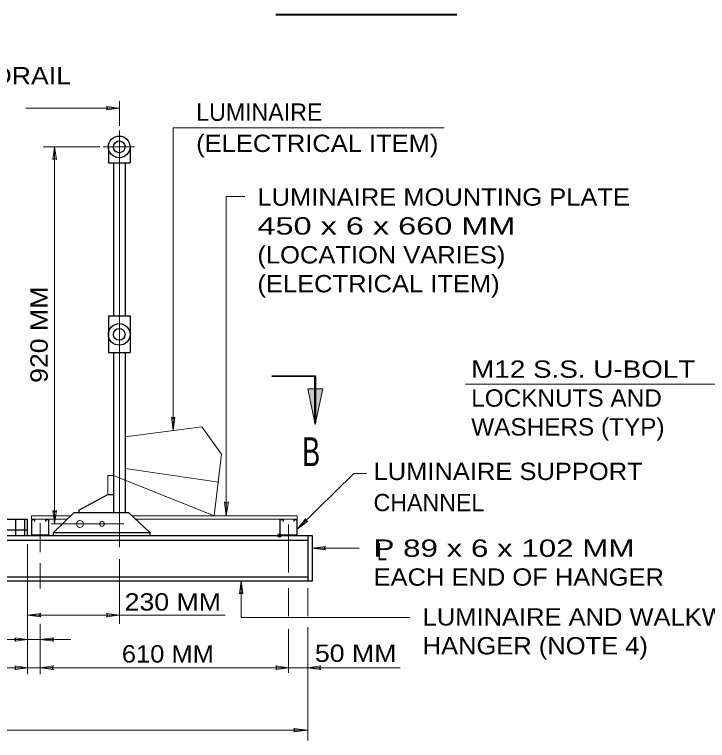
# Model space of a CAD drawing. Extents: x 312601.858 to 312602.699, y 144420.109 to 144420.704.
# Drawn here: x 312602.0414 to 312602.1613, y 144420.4587 to 144420.5844 of the extents above; entities that cross this region are included whole.
import ezdxf
from ezdxf.enums import TextEntityAlignment as Align

# ---------------------------------------------------------------- set-up
doc = ezdxf.new("R2010")
doc.units = 0
doc.header["$LTSCALE"] = 0.0012
doc.header["$PDMODE"] = 32
doc.header["$PDSIZE"] = 0.0006
doc.linetypes.add('DOT_DASHED', pattern=[7.7, 5, -1.2, 0.3, -1.2])
doc.linetypes.add('LONG_DASHED', pattern=[7.5, 6, -1.5])
for name, color, linetype, lineweight in [('1', 7, 'Continuous', 13), ('2', 7, 'Continuous', 13), ('39', 7, 'Continuous', 13), ('5', 7, 'Continuous', 25)]:
    doc.layers.add(name, color=color, linetype=linetype, lineweight=lineweight)

msp = doc.modelspace()

# ---------------------------------------------------------------- hatches: boundary and pattern name
at = {"layer": '1'}
for points in [[(312602.0921, 144420.5196), (312602.0934, 144420.5196), (312602.0934, 144420.5134)], [(312602.0921, 144420.5196), (312602.0934, 144420.5196), (312602.0934, 144420.5134)], [(312602.0947, 144420.5196), (312602.0934, 144420.5196), (312602.0934, 144420.5134)], [(312602.0947, 144420.5196), (312602.0934, 144420.5196), (312602.0934, 144420.5134)]]:
    msp.add_hatch(color=256, dxfattribs=at).paths.add_polyline_path(points)
at = {"layer": '39'}
for points in [[(312602.078, 144420.4998), (312602.0784, 144420.5), (312602.078, 144420.4976), (312602.0777, 144420.5)], [(312602.0899, 144420.4605), (312602.0897, 144420.4608), (312602.0921, 144420.4605), (312602.0897, 144420.4602)], [(312602.0899, 144420.4605), (312602.0897, 144420.4608), (312602.0921, 144420.4605), (312602.0897, 144420.4602)]]:
    msp.add_hatch(color=256, dxfattribs=at).paths.add_polyline_path(points)

# ---------------------------------------------------------------- linework, layer by layer
at = {"layer": '1'}
for p, q in [((312602.0595, 144420.5694), (312602.0595, 144420.5651)), ((312602.0433, 144420.5682), (312602.0595, 144420.5682)), ((312602.0688, 144420.5648), (312602.1157, 144420.5648)), ((312602.0688, 144420.5648), (312602.0688, 144420.5124)), ((312602.0463, 144420.5615), (312602.0561, 144420.5615)), ((312602.0483, 144420.5615), (312602.0483, 144420.4962)), ((312602.078, 144420.5529), (312602.078, 144420.4976)), ((312602.078, 144420.5529), (312602.0812, 144420.5529)), ((312602.0935, 144420.5137), (312602.0935, 144420.5217)), ((312602.1194, 144420.5204), (312602.1734, 144420.5204)), ((312602.0903, 144420.4976), (312602.0903, 144420.497)), ((312602.0477, 144420.4962), (312602.0603, 144420.4962)), ((312602.0436, 144420.4702), (312602.0436, 144420.4927)), ((312602.0929, 144420.492), (312602.101, 144420.492)), ((312602.0595, 144420.4901), (312602.0595, 144420.4789)), ((312602.0458, 144420.4894), (312602.0458, 144420.485)), ((312602.0806, 144420.48), (312602.0806, 144420.4863)), ((312602.0921, 144420.4851), (312602.0921, 144420.4802)), ((312602.0436, 144420.4804), (312602.0778, 144420.4804)), ((312602.0806, 144420.48), (312602.1098, 144420.48)), ((312602.0458, 144420.4789), (312602.0458, 144420.4702)), ((312602.0888, 144420.478), (312602.0888, 144420.4704)), ((312602.0921, 144420.4783), (312602.0921, 144420.4587)), ((312601.9943, 144420.4713), (312602.0436, 144420.4713)), ((312602.0436, 144420.4713), (312602.0888, 144420.4713)), ((312601.967, 144420.4605), (312602.0921, 144420.4605))]:
    msp.add_line(p, q, dxfattribs=at)
at = {"layer": '1', "linetype": 'DOT_DASHED'}
for p, q in [((312602.0595, 144420.5643), (312602.0595, 144420.4922)), ((312602.0567, 144420.5615), (312602.0621, 144420.5615)), ((312602.0458, 144420.4963), (312602.0458, 144420.4913)), ((312602.0888, 144420.4961), (312602.0888, 144420.4878)), ((312602.0888, 144420.4851), (312602.0888, 144420.4802))]:
    msp.add_line(p, q, dxfattribs=at)
at = {"layer": '1', "lineweight": 25}
for p, q in [((312602.0576, 144420.5615), (312602.0576, 144420.5587)), ((312602.0614, 144420.5615), (312602.0614, 144420.5587)), ((312602.0576, 144420.5587), (312602.0614, 144420.5587)), ((312602.0585, 144420.5587), (312602.0585, 144420.5322)), ((312602.0605, 144420.5587), (312602.0605, 144420.5322)), ((312602.0576, 144420.5322), (312602.0614, 144420.5322)), ((312602.0576, 144420.5322), (312602.0576, 144420.5259)), ((312602.0614, 144420.5322), (312602.0614, 144420.5259)), ((312602.0576, 144420.5259), (312602.0614, 144420.5259)), ((312602.0585, 144420.5259), (312602.0585, 144420.4982)), ((312602.0605, 144420.5259), (312602.0605, 144420.4982)), ((312602.0525, 144420.4986), (312602.0575, 144420.5013)), ((312602.0575, 144420.5013), (312602.0585, 144420.5013)), ((312602.0525, 144420.4986), (312602.0525, 144420.4982)), ((312602.0517, 144420.4982), (312602.0481, 144420.4947)), ((312602.0517, 144420.4982), (312602.0611, 144420.4982)), ((312602.0648, 144420.4947), (312602.0611, 144420.4982)), ((312601.9943, 144420.497), (312602.0436, 144420.497)), ((312602.0415, 144420.497), (312602.0415, 144420.4942)), ((312602.0431, 144420.497), (312602.0431, 144420.4942)), ((312602.0436, 144420.4942), (312602.0436, 144420.497)), ((312601.9943, 144420.4952), (312602.0436, 144420.4952)), ((312601.9917, 144420.4942), (312602.0929, 144420.4942)), ((312602.0481, 144420.4942), (312602.0481, 144420.4947)), ((312602.0481, 144420.4947), (312602.0648, 144420.4947)), ((312602.0648, 144420.4947), (312602.0648, 144420.4942)), ((312602.0921, 144420.4942), (312602.0921, 144420.4863)), ((312602.0929, 144420.4942), (312602.0929, 144420.4863)), ((312601.967, 144420.4934), (312602.0921, 144420.4934)), ((312602.0929, 144420.4863), (312601.9662, 144420.4863)), ((312602.0921, 144420.487), (312601.967, 144420.487))]:
    msp.add_line(p, q, dxfattribs=at)
at = {"layer": '1', "linetype": 'LONG_DASHED'}
for p, q in [((312602.0605, 144420.5113), (312602.0738, 144420.513)), ((312602.0738, 144420.513), (312602.0772, 144420.5083)), ((312602.0759, 144420.4976), (312602.0772, 144420.5083)), ((312602.0605, 144420.5058), (312602.0767, 144420.5034)), ((312602.0575, 144420.5013), (312602.0575, 144420.5046)), ((312602.0443, 144420.4976), (312602.0511, 144420.4976)), ((312602.0616, 144420.4976), (312602.0903, 144420.4976)), ((312602.0443, 144420.497), (312602.0505, 144420.497)), ((312602.0624, 144420.497), (312602.0903, 144420.497))]:
    msp.add_line(p, q, dxfattribs=at)
at = {"layer": '1'}
for points in [[(312602.0573, 144420.5685), (312602.0595, 144420.5682), (312602.0573, 144420.5679), (312602.0575, 144420.5682)], [(312602.048, 144420.5593), (312602.0483, 144420.5615), (312602.0486, 144420.5593), (312602.0483, 144420.5595)], [(312602.0921, 144420.5196), (312602.0934, 144420.5196), (312602.0934, 144420.5134)], [(312602.0921, 144420.5196), (312602.0934, 144420.5196), (312602.0934, 144420.5134)], [(312602.0947, 144420.5196), (312602.0934, 144420.5196), (312602.0934, 144420.5134)], [(312602.0947, 144420.5196), (312602.0934, 144420.5196), (312602.0934, 144420.5134)], [(312602.0691, 144420.5147), (312602.0688, 144420.5124), (312602.0685, 144420.5147), (312602.0688, 144420.5144)], [(312602.0486, 144420.4985), (312602.0483, 144420.4962), (312602.048, 144420.4985), (312602.0483, 144420.4982)], [(312602.0921, 144420.4967), (312602.0903, 144420.4953), (312602.0917, 144420.4971), (312602.0917, 144420.4967)], [(312602.0952, 144420.4917), (312602.0929, 144420.492), (312602.0952, 144420.4923), (312602.0949, 144420.492)], [(312602.0803, 144420.4841), (312602.0806, 144420.4863), (312602.0809, 144420.4841), (312602.0806, 144420.4843)], [(312602.0459, 144420.4801), (312602.0436, 144420.4804), (312602.0459, 144420.4807), (312602.0456, 144420.4804)], [(312602.0573, 144420.4807), (312602.0595, 144420.4804), (312602.0573, 144420.4801), (312602.0575, 144420.4804)], [(312602.0414, 144420.4765), (312602.0436, 144420.4762), (312602.0414, 144420.4759), (312602.0416, 144420.4762)], [(312602.0481, 144420.4759), (312602.0458, 144420.4762), (312602.0481, 144420.4765), (312602.0478, 144420.4762)], [(312602.0414, 144420.4716), (312602.0436, 144420.4713), (312602.0414, 144420.471), (312602.0416, 144420.4713)], [(312602.0481, 144420.471), (312602.0458, 144420.4713), (312602.0481, 144420.4716), (312602.0478, 144420.4713)], [(312602.0866, 144420.4716), (312602.0888, 144420.4713), (312602.0866, 144420.471), (312602.0868, 144420.4713)], [(312602.0944, 144420.471), (312602.0921, 144420.4713), (312602.0944, 144420.4716), (312602.0941, 144420.4713)]]:
    msp.add_lwpolyline(points, close=True, dxfattribs=at)
at = {"layer": '1', "lineweight": 35}
msp.add_lwpolyline([(312602.0934, 144420.5196), (312602.0934, 144420.5218), (312602.0859, 144420.5218)], dxfattribs=at)
msp.add_lwpolyline([(312602.0934, 144420.5196), (312602.0934, 144420.5218), (312602.0859, 144420.5218)], dxfattribs=at)
at = {"layer": '1'}
for points in [[(312602.0933, 144420.5219), (312602.0933, 144420.5137), (312602.0935, 144420.5217)], [(312602.0905, 144420.4955), (312602.1001, 144420.5049), (312602.1023, 144420.5049)], [(312602.0269, 144420.4762), (312602.0436, 144420.4762), (312602.0458, 144420.4762), (312602.0511, 144420.4762)], [(312602.0888, 144420.4713), (312602.0921, 144420.4713), (312602.1081, 144420.4713)]]:
    msp.add_lwpolyline(points, dxfattribs=at)
at = {"layer": '1', "linetype": 'LONG_DASHED'}
msp.add_lwpolyline([(312602.0575, 144420.5046), (312602.0585, 144420.5046), (312602.0759, 144420.4976)], dxfattribs=at)
at = {"layer": '1', "lineweight": 25}
for centre, radius in [((312602.05948, 144420.56148), 0.00187), ((312602.05948, 144420.56148), 0.00102), ((312602.05948, 144420.52901), 0.00187), ((312602.05948, 144420.52901), 0.00102)]:
    msp.add_circle(centre, radius, dxfattribs=at)
at = {"layer": '1'}
for centre, radius in [((312602.05268, 144420.4962), 0.000595), ((312602.056505, 144420.4962), 0.000425)]:
    msp.add_circle(centre, radius, dxfattribs=at)
at = {"layer": '2', "lineweight": 40}
msp.add_line((312602.0866, 144420.5844), (312602.1179, 144420.5844), dxfattribs=at)
at = {"layer": '39'}
for points in [[(312602.078, 144420.4998), (312602.0784, 144420.5), (312602.078, 144420.4976), (312602.0777, 144420.5)], [(312602.0899, 144420.4605), (312602.0897, 144420.4608), (312602.0921, 144420.4605), (312602.0897, 144420.4602)], [(312602.0899, 144420.4605), (312602.0897, 144420.4608), (312602.0921, 144420.4605), (312602.0897, 144420.4602)]]:
    msp.add_lwpolyline(points, close=True, dxfattribs=at)
at = {"layer": '5', "lineweight": 13}
for p, q in [((312602.0443, 144420.497), (312602.0443, 144420.4976)), ((312602.0872, 144420.4942), (312602.0873, 144420.4942))]:
    msp.add_line(p, q, dxfattribs=at)
at = {"layer": '5'}
for p, q in [((312602.0443, 144420.4969), (312602.0443, 144420.4943)), ((312602.0473, 144420.4943), (312602.0473, 144420.4969)), ((312602.0873, 144420.4969), (312602.0873, 144420.4943)), ((312602.0903, 144420.4943), (312602.0903, 144420.4969)), ((312602.0443, 144420.4943), (312602.0473, 144420.4943)), ((312602.0873, 144420.4943), (312602.0903, 144420.4943))]:
    msp.add_line(p, q, dxfattribs=at)
for points in [[(312602.0449, 144420.4966), (312602.0449, 144420.4969), (312602.0443, 144420.4969)], [(312602.0473, 144420.4969), (312602.0467, 144420.4969), (312602.0467, 144420.4966)], [(312602.0879, 144420.4966), (312602.0879, 144420.4969), (312602.0873, 144420.4969)], [(312602.0903, 144420.4969), (312602.0897, 144420.4969), (312602.0897, 144420.4966)]]:
    msp.add_lwpolyline(points, dxfattribs=at)
msp.add_point((312602.0872, 144420.4942), dxfattribs=at)

# ---------------------------------------------------------------- texts
at = {"layer": '2'}
for s, width, p in [('C OF HANDRAIL ', 1.15, (312602.0155, 144420.5723)), ('(ELECTRICAL ITEM)', 1.1, (312602.0728, 144420.5606)), ('LUMINAIRE MOUNTING PLATE', 1.1, (312602.0834, 144420.5513)), ('450 x 6 x 660 MM', 1.4, (312602.0834, 144420.5463)), ('(LOCATION VARIES)', 1.1, (312602.0834, 144420.5413)), ('(ELECTRICAL ITEM)', 1.1, (312602.0834, 144420.5363)), ('M12 S.S. U-BOLT', 1.2, (312602.1204, 144420.5215)), ('LOCKNUTS AND', 1.05, (312602.1204, 144420.5165)), ('WASHERS (TYP)', 1.05, (312602.1204, 144420.5115)), ('LUMINAIRE SUPPORT', 1.1, (312602.1035, 144420.5038)), ('P 89 x 6 x 102 MM', 1.35, (312602.1035, 144420.4905)), ('EACH END OF HANGER ', 1.1, (312602.1035, 144420.4855)), ('LUMINAIRE AND WALKWAY', 1.1, (312602.112, 144420.4786)), ('HANGER (NOTE 4)', 1.1, (312602.112, 144420.4736))]:
    msp.add_text(s, height=0.003, dxfattribs=dict(at, width=width)).set_placement(p)
for s, p in [('LUMINAIRE', (312602.0728, 144420.566)), ('CHANNEL', (312602.1035, 144420.4984))]:
    msp.add_text(s, height=0.003, dxfattribs=at).set_placement(p)
at = {"layer": '2', "width": 1.15}
msp.add_text('920 MM', height=0.003, rotation=90, dxfattribs=at).set_placement((312602.0471, 144420.52895), align=Align.CENTER)
at = {"layer": '2'}
for s, height, width, p in [('B', 0.005, 0.7, (312602.0927, 144420.5062)), ('L', 0.003, 0.75, (312602.10495, 144420.4899)), ('230 MM', 0.003, 1.15, (312602.06875, 144420.4812)), ('610 MM', 0.003, 1.1, (312602.0679, 144420.4722)), ('50 MM', 0.003, 1.15, (312602.1004, 144420.4723))]:
    msp.add_text(s, height=height, dxfattribs=dict(at, width=width)).set_placement(p, align=Align.CENTER)

doc.saveas('drawing.dxf')
